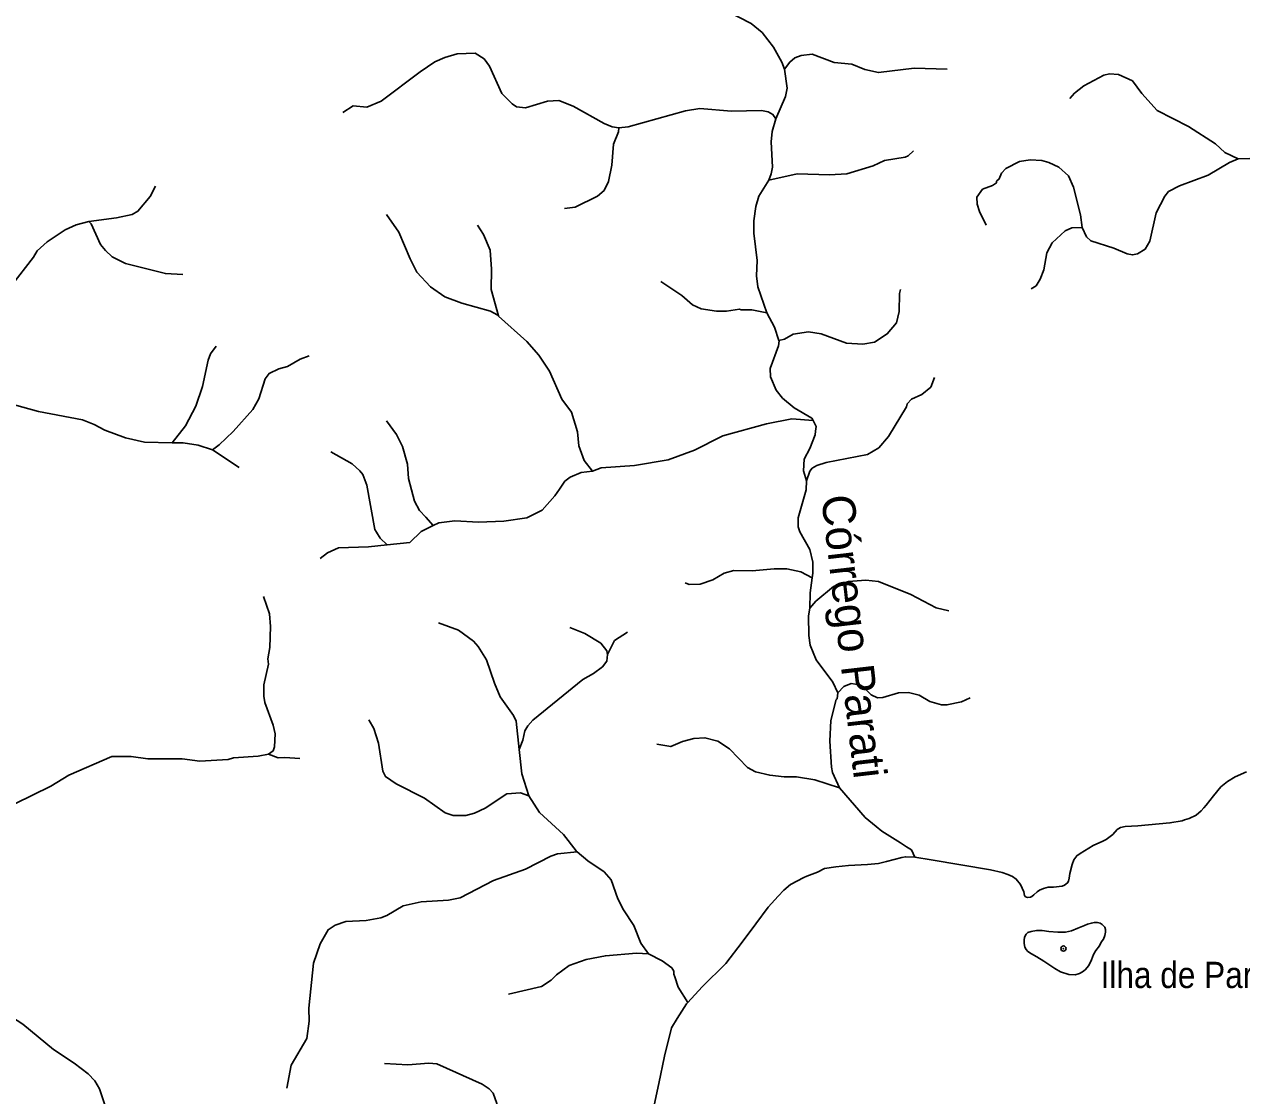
# Model space of a CAD drawing. Extents: x 317.8 to 344.1, y 7676.8 to 7704.8.
# Drawn here: x 330.394 to 334.107, y 7697.935 to 7701.2 of the extents above; entities that cross this region are included whole.
import ezdxf
from ezdxf.enums import TextEntityAlignment as Align

# ---------------------------------------------------------------- set-up
doc = ezdxf.new("R2010")
doc.units = 0
doc.header["$LTSCALE"] = 0.032
doc.header["$PDMODE"] = 32
doc.header["$PDSIZE"] = 0.016
doc.layers.add('2', color=7, linetype='Continuous', lineweight=25)
doc.layers.add('7', color=7, linetype='Continuous', lineweight=25)
doc.layers.add('54', color=7, linetype='Continuous')
doc.layers.add('61', color=7, linetype='Continuous')

msp = doc.modelspace()

# ---------------------------------------------------------------- linework, layer by layer
at = {"layer": '2'}
for points in [[(333.11, 7698.662), (333.1596, 7698.6537), (333.3404, 7698.6227), (333.3766, 7698.6155), (333.3931, 7698.6093), (333.4076, 7698.6031), (333.4189, 7698.5948), (333.4323, 7698.5783), (333.4375, 7698.5669), (333.4427, 7698.5556), (333.4447, 7698.5452), (333.4478, 7698.5411), (333.453, 7698.539), (333.4623, 7698.5401), (333.4664, 7698.5421), (333.4726, 7698.5473), (333.483, 7698.5556), (333.4902, 7698.5607), (333.5026, 7698.5659), (333.516, 7698.57), (333.5326, 7698.57), (333.5594, 7698.5731), (333.5666, 7698.5762), (333.5759, 7698.5835), (333.578, 7698.5886), (333.5801, 7698.5979), (333.5821, 7698.6124), (333.5894, 7698.6392), (333.5945, 7698.6537), (333.6038, 7698.6661), (333.6142, 7698.6733), (333.6534, 7698.6971), (333.6836, 7698.711), (333.6937, 7698.7157), (333.7133, 7698.7312), (333.7268, 7698.7456), (333.7371, 7698.7518), (333.7516, 7698.7549), (333.7898, 7698.757), (333.8879, 7698.7663), (333.9251, 7698.7725), (333.9328, 7698.7751), (333.9468, 7698.7797), (333.9675, 7698.7901), (333.983, 7698.8025), (333.9912, 7698.8118), (333.9985, 7698.82), (334.0212, 7698.8489), (334.0429, 7698.8758), (334.0635, 7698.8923), (334.0873, 7698.9068), (334.1214, 7698.9223)], [(332.4175, 7698.2188), (332.4613, 7698.2663), (332.5336, 7698.3376), (332.5832, 7698.4027), (332.6245, 7698.4585), (332.6627, 7698.5091), (332.6927, 7698.5432), (332.7102, 7698.5607), (332.7309, 7698.5783), (332.7712, 7698.6), (332.7803, 7698.6036), (332.8125, 7698.6165), (332.8342, 7698.6268), (332.8693, 7698.632), (332.9076, 7698.6361), (332.9654, 7698.6392), (332.9985, 7698.6423), (333.0233, 7698.6485), (333.0697, 7698.6609), (333.0813, 7698.663), (333.11, 7698.662)], [(332.2426, 7697.6209), (332.2547, 7697.6465), (332.2733, 7697.6795), (332.2805, 7697.7054), (332.2836, 7697.726), (332.2888, 7697.7694), (332.296, 7697.8242), (332.3001, 7697.8541), (332.3084, 7697.881), (332.3146, 7697.9058), (332.329, 7697.9719), (332.3466, 7698.0556), (332.3673, 7698.1413), (332.3848, 7698.1702), (332.4138, 7698.2147), (332.4175, 7698.2188)]]:
    msp.add_lwpolyline(points, dxfattribs=at)
msp.add_lwpolyline([(333.6732, 7698.3918), (333.662, 7698.3776), (333.6549, 7698.3652), (333.6484, 7698.3487), (333.6401, 7698.3316), (333.6289, 7698.3186), (333.6212, 7698.3126), (333.6123, 7698.3073), (333.5987, 7698.3032), (333.5798, 7698.3044), (333.5544, 7698.3126), (333.5373, 7698.3221), (333.5036, 7698.3446), (333.4823, 7698.3576), (333.4658, 7698.367), (333.4546, 7698.3747), (333.4493, 7698.38), (333.4451, 7698.3877), (333.4428, 7698.3989), (333.4428, 7698.4084), (333.4439, 7698.4184), (333.4493, 7698.4273), (333.4546, 7698.432), (333.4646, 7698.4355), (333.4806, 7698.4379), (333.4977, 7698.4379), (333.519, 7698.4355), (333.5456, 7698.4332), (333.5692, 7698.4332), (333.5875, 7698.4373), (333.607, 7698.445), (333.6271, 7698.4539), (333.6366, 7698.458), (333.6484, 7698.461), (333.6572, 7698.4621), (333.6673, 7698.4621), (333.675, 7698.4604), (333.6815, 7698.4562), (333.6891, 7698.4485), (333.6909, 7698.4409), (333.6909, 7698.4332), (333.6897, 7698.4231), (333.6856, 7698.4119), (333.6785, 7698.4025)], close=True, dxfattribs=at)
at = {"layer": '54'}
msp.add_point((333.563, 7698.3831), dxfattribs=at)
at = {"layer": '7'}
msp.add_line((330.9677, 7699.9037), (331.0485, 7699.8496), dxfattribs=at)
for points in [[(332.7127, 7701.0636), (332.7039, 7701.0855), (332.6788, 7701.1305), (332.6437, 7701.1753), (332.6105, 7701.2027), (332.5375, 7701.2407), (332.4622, 7701.2695), (332.4081, 7701.2981), (332.3644, 7701.3109), (332.3427, 7701.3133), (332.2463, 7701.3044), (332.2335, 7701.3067), (332.1926, 7701.3243), (332.1788, 7701.3361), (332.1388, 7701.3581)], [(332.2074, 7700.8853), (332.1868, 7700.8884), (332.1625, 7700.8976), (332.068, 7700.9506), (332.024, 7700.9685), (331.9895, 7700.9661), (331.9219, 7700.9459), (331.8949, 7700.9493), (331.882, 7700.9583), (331.8504, 7700.99), (331.8122, 7701.0727), (331.7959, 7701.0955), (331.7684, 7701.1121), (331.7143, 7701.1103), (331.6758, 7701.0991), (331.6461, 7701.086), (331.601, 7701.056), (331.482, 7700.9657), (331.4387, 7700.9474), (331.3966, 7700.9522), (331.3648, 7700.932)], [(333.2083, 7701.0632), (333.1073, 7701.0663), (332.9985, 7701.0534), (332.9576, 7701.063), (332.9174, 7701.0786), (332.8633, 7701.0844), (332.7967, 7701.1095), (332.7628, 7701.1056), (332.744, 7701.0979), (332.7283, 7701.0851), (332.7127, 7701.0636)], [(332.6854, 7700.9119), (332.7153, 7700.9805), (332.7199, 7701.0062), (332.7127, 7701.0636)], [(334.0962, 7700.7904), (334.0558, 7700.8097), (334.0268, 7700.8363), (333.9445, 7700.8886), (333.8487, 7700.938), (333.8026, 7700.9895), (333.7734, 7701.0285), (333.7306, 7701.0476), (333.7039, 7701.0492), (333.686, 7701.0457), (333.6256, 7701.0126), (333.5973, 7700.9908), (333.5824, 7700.9744)], [(332.6854, 7700.9119), (332.6771, 7700.9256), (332.6627, 7700.9336), (332.6422, 7700.9376), (332.5509, 7700.936), (332.454, 7700.9433), (332.4099, 7700.937), (332.2358, 7700.8884), (332.2074, 7700.8853)], [(332.6644, 7700.7251), (332.672, 7700.7444), (332.6752, 7700.7648), (332.6719, 7700.8423), (332.6747, 7700.8739), (332.6854, 7700.9119)], [(332.2074, 7700.8853), (332.2061, 7700.8722), (332.1911, 7700.8352), (332.1853, 7700.7714), (332.1757, 7700.7216), (332.1626, 7700.6942), (332.1422, 7700.6763), (332.0742, 7700.6433), (332.0412, 7700.6394)], [(332.6644, 7700.7251), (332.7511, 7700.7446), (332.8493, 7700.7421), (332.9023, 7700.7444), (332.983, 7700.7693), (333.0168, 7700.7851), (333.0805, 7700.7955), (333.0898, 7700.7995), (333.1056, 7700.8146)], [(334.4543, 7700.8018), (334.4243, 7700.8022), (334.3602, 7700.7926), (334.3358, 7700.7841), (334.2942, 7700.7795), (334.1956, 7700.786), (334.1728, 7700.7828), (334.1316, 7700.7909), (334.0962, 7700.7904)], [(333.6198, 7700.5808), (333.6149, 7700.6197), (333.5942, 7700.7044), (333.5786, 7700.7381), (333.5494, 7700.765), (333.519, 7700.7793), (333.4967, 7700.785), (333.4614, 7700.7876), (333.4291, 7700.7827), (333.3872, 7700.7611), (333.3737, 7700.747), (333.367, 7700.7291), (333.3593, 7700.7218), (333.3586, 7700.7172), (333.3465, 7700.709), (333.3163, 7700.698), (333.2988, 7700.6731), (333.2996, 7700.652), (333.3066, 7700.6296), (333.3273, 7700.588)], [(334.0962, 7700.7904), (334.0698, 7700.7794), (334.0044, 7700.7408), (333.917, 7700.7083), (333.8838, 7700.6905), (333.8719, 7700.6763), (333.8462, 7700.626), (333.8268, 7700.5399), (333.8121, 7700.5155), (333.789, 7700.5008), (333.7738, 7700.4976), (333.7571, 7700.5006), (333.7163, 7700.5177), (333.6468, 7700.54), (333.6337, 7700.5525), (333.6198, 7700.5808)], [(332.6587, 7700.3206), (332.6312, 7700.3997), (332.6264, 7700.4336), (332.6287, 7700.4804), (332.6189, 7700.5638), (332.619, 7700.601), (332.6253, 7700.6446), (332.6337, 7700.6768), (332.6644, 7700.7251)], [(330.7942, 7700.707), (330.7776, 7700.676), (330.7401, 7700.6308), (330.7227, 7700.6211), (330.6743, 7700.6102), (330.5901, 7700.599)], [(331.8398, 7700.3113), (331.8363, 7700.3145), (331.8151, 7700.3264), (331.7279, 7700.3507), (331.6766, 7700.3698), (331.6328, 7700.3998), (331.5912, 7700.4448), (331.5705, 7700.4851), (331.5356, 7700.5668), (331.4984, 7700.6206)], [(330.5901, 7700.599), (330.5521, 7700.5887), (330.518, 7700.5741), (330.4634, 7700.537), (330.433, 7700.5098), (330.4213, 7700.4904), (330.3551, 7700.4049), (330.3124, 7700.3604), (330.2822, 7700.334), (330.2402, 7700.3139), (330.1985, 7700.2994), (330.1287, 7700.2979), (330.1009, 7700.293), (330.0589, 7700.2801), (330.0305, 7700.2538), (330.006, 7700.2037), (329.9865, 7700.1871), (329.986, 7700.1867)], [(330.8774, 7700.4373), (330.824, 7700.4405), (330.7023, 7700.4714), (330.662, 7700.4914), (330.6409, 7700.5105), (330.6264, 7700.529), (330.5978, 7700.5926), (330.5901, 7700.599)], [(331.8398, 7700.3113), (331.8398, 7700.3114), (331.8171, 7700.3916), (331.8186, 7700.4542), (331.8145, 7700.5122), (331.7938, 7700.5602), (331.7755, 7700.588)], [(333.6198, 7700.5808), (333.5884, 7700.5797), (333.5682, 7700.5707), (333.5289, 7700.5346), (333.5123, 7700.504), (333.5033, 7700.4522), (333.4924, 7700.4237), (333.4802, 7700.4036), (333.4651, 7700.3941)], [(332.6587, 7700.3206), (332.6128, 7700.3296), (332.5798, 7700.3297), (332.5747, 7700.3321), (332.5352, 7700.3264), (332.5051, 7700.3263), (332.4581, 7700.3332), (332.4318, 7700.3454), (332.3995, 7700.3738), (332.3346, 7700.4169)], [(333.0665, 7700.3924), (333.0631, 7700.3802), (333.0625, 7700.3246), (333.0539, 7700.2902), (333.0259, 7700.2565), (332.9871, 7700.2317), (332.9509, 7700.2252), (332.9014, 7700.2285), (332.8241, 7700.2571), (332.7856, 7700.2628), (332.7387, 7700.2563), (332.7124, 7700.2406), (332.695, 7700.2371)], [(332.695, 7700.2371), (332.6819, 7700.2771), (332.6587, 7700.3206)], [(332.127, 7699.8386), (332.1016, 7699.8713), (332.0845, 7699.9153), (332.081, 7699.958), (332.0624, 7700.0186), (332.0335, 7700.0581), (331.9957, 7700.1435), (331.9633, 7700.1924), (331.9265, 7700.2332), (331.8398, 7700.3113)], [(330.9784, 7700.2197), (330.9619, 7700.1956), (330.9542, 7700.1771), (330.9373, 7700.0969), (330.9172, 7700.0362), (330.8854, 7699.977), (330.8445, 7699.9252)], [(332.7994, 7699.9923), (332.7953, 7699.9998), (332.7422, 7700.0314), (332.7062, 7700.0605), (332.6871, 7700.0851), (332.6696, 7700.1262), (332.6688, 7700.151), (332.6943, 7700.2205), (332.6955, 7700.2357), (332.695, 7700.2371)], [(330.9677, 7699.9037), (330.9879, 7699.9186), (331.0304, 7699.9594), (331.0906, 7700.0264), (331.1088, 7700.0587), (331.1277, 7700.1198), (331.1403, 7700.1362), (331.1699, 7700.1503), (331.196, 7700.1569), (331.2347, 7700.1796), (331.2621, 7700.1895)], [(330.8445, 7699.9252), (330.7604, 7699.927), (330.7019, 7699.94), (330.6389, 7699.9633), (330.6067, 7699.9807), (330.5708, 7699.9944), (330.4365, 7700.0198), (330.2922, 7700.0601), (330.2584, 7700.0737), (330.1936, 7700.0901), (330.1781, 7700.0957)], [(333.17, 7700.1235), (333.1582, 7700.0947), (333.1314, 7700.0722), (333.0999, 7700.0573), (333.086, 7700.0433), (333.0841, 7700.0345), (333.0299, 7699.9436), (332.9998, 7699.9093), (332.9656, 7699.8894), (332.8397, 7699.8652), (332.8104, 7699.8555), (332.7967, 7699.8472), (332.7899, 7699.8385), (332.7789, 7699.8092)], [(331.641, 7699.6728), (331.6183, 7699.6977), (331.5994, 7699.7184), (331.5836, 7699.747), (331.5653, 7699.8157), (331.562, 7699.8596), (331.5472, 7699.9139), (331.5283, 7699.9499), (331.4984, 7699.9915)], [(332.127, 7699.8386), (332.153, 7699.8482), (332.2546, 7699.8553), (332.3575, 7699.873), (332.4373, 7699.9022), (332.5199, 7699.9435), (332.5241, 7699.9456), (332.6573, 7699.9826), (332.7347, 7699.9979), (332.7994, 7699.9923)], [(332.7789, 7699.8092), (332.7705, 7699.8395), (332.7723, 7699.8748), (332.7893, 7699.9076), (332.8058, 7699.9494), (332.8073, 7699.9606), (332.8091, 7699.9747), (332.7994, 7699.9923)], [(330.9677, 7699.9037), (330.9234, 7699.9173), (330.8781, 7699.9245), (330.8445, 7699.9252)], [(331.3289, 7699.8969), (331.3932, 7699.8609), (331.4174, 7699.8393), (331.4256, 7699.8279), (331.438, 7699.7954), (331.4628, 7699.6608), (331.4681, 7699.652), (331.4791, 7699.6336), (331.5005, 7699.6139)], [(332.127, 7699.8386), (332.0922, 7699.8339), (332.0582, 7699.8204), (332.0427, 7699.8078), (332.026, 7699.7837), (332.0115, 7699.7629), (331.9732, 7699.7196), (331.926, 7699.696), (331.8564, 7699.6858), (331.779, 7699.6825), (331.7065, 7699.6874), (331.658, 7699.6809), (331.641, 7699.6728)], [(332.7969, 7699.5127), (332.799, 7699.5273), (332.7982, 7699.5606), (332.7899, 7699.5999), (332.759, 7699.6532), (332.7543, 7699.6687), (332.7544, 7699.6958), (332.7779, 7699.7813), (332.7789, 7699.8092)], [(331.641, 7699.6728), (331.6036, 7699.6549), (331.5695, 7699.6214), (331.5005, 7699.6139)], [(331.5005, 7699.6139), (331.4431, 7699.6076), (331.3518, 7699.6049), (331.3185, 7699.5897), (331.2963, 7699.5725)], [(332.7969, 7699.5127), (332.7618, 7699.5311), (332.7191, 7699.5406), (332.6809, 7699.5406), (332.6137, 7699.5342), (332.5576, 7699.5358), (332.5278, 7699.5276), (332.4932, 7699.5071), (332.4551, 7699.4935), (332.4214, 7699.4927), (332.4096, 7699.4976)], [(332.7893, 7699.4206), (332.7902, 7699.4673), (332.7969, 7699.5127)], [(332.7893, 7699.4206), (332.808, 7699.442), (332.8614, 7699.4868), (332.9079, 7699.5024), (332.96, 7699.5065), (332.9985, 7699.5016), (333.0979, 7699.4626), (333.1753, 7699.4218), (333.2132, 7699.4128)], [(331.1235, 7699.4568), (331.1413, 7699.4037), (331.1447, 7699.365), (331.1421, 7699.3012), (331.1365, 7699.2668), (331.1379, 7699.2496), (331.1243, 7699.187), (331.1243, 7699.1528), (331.1276, 7699.1333), (331.1528, 7699.0644), (331.1583, 7699.0377), (331.157, 7698.9978), (331.153, 7698.986), (331.1384, 7698.976)], [(332.8749, 7699.1624), (332.8596, 7699.1948), (332.809, 7699.2633), (332.7908, 7699.3083), (332.7869, 7699.3378), (332.7853, 7699.3969), (332.7893, 7699.4206)], [(331.6565, 7699.3761), (331.7175, 7699.3538), (331.7632, 7699.3206), (331.7778, 7699.3043), (331.8038, 7699.263), (331.8274, 7699.1925), (331.8449, 7699.1508), (331.8859, 7699.0937), (331.8935, 7699.0764), (331.903, 7698.9897)], [(332.1726, 7699.2791), (332.1707, 7699.2909), (332.1518, 7699.3143), (332.103, 7699.3434), (332.0575, 7699.3615)], [(332.1726, 7699.2791), (332.1934, 7699.3221), (332.2336, 7699.3476)], [(331.903, 7698.9897), (331.9144, 7699.0181), (331.9204, 7699.0465), (331.9295, 7699.0622), (331.9446, 7699.079), (332.0972, 7699.2038), (332.13, 7699.222), (332.1572, 7699.242), (332.1703, 7699.2588), (332.1726, 7699.2791)], [(333.2784, 7699.1471), (333.2521, 7699.1354), (333.2079, 7699.1259), (333.1912, 7699.1259), (333.156, 7699.1362), (333.1234, 7699.1555), (333.09, 7699.1641), (333.0604, 7699.1625), (333.0121, 7699.1487), (332.9959, 7699.1479), (332.9771, 7699.1568), (332.9512, 7699.1822), (332.9418, 7699.1868), (332.9157, 7699.1911), (332.8929, 7699.182), (332.8749, 7699.1624)], [(332.8802, 7698.8731), (332.859, 7698.92), (332.8554, 7698.9363), (332.8504, 7699.015), (332.8538, 7699.0784), (332.8701, 7699.1419), (332.8733, 7699.1444), (332.8749, 7699.1624)], [(331.4446, 7699.0803), (331.4595, 7699.0543), (331.4743, 7699.0092), (331.4871, 7698.9241), (331.4953, 7698.9072), (331.5282, 7698.8856), (331.6143, 7698.8417), (331.6771, 7698.7964), (331.7014, 7698.7885), (331.7401, 7698.7892), (331.7672, 7698.796), (331.7994, 7698.8106), (331.8651, 7698.8544), (331.9067, 7698.8576), (331.9322, 7698.849)], [(332.8802, 7698.8731), (332.8048, 7698.8976), (332.7485, 7698.9065), (332.7116, 7698.9066), (332.6672, 7698.9115), (332.624, 7698.9218), (332.5997, 7698.9346), (332.545, 7698.9918), (332.5088, 7699.0155), (332.4694, 7699.0256), (332.4361, 7699.0231), (332.4016, 7699.0139), (332.3652, 7698.9987), (332.3232, 7699.0061)], [(331.903, 7698.9897), (331.9111, 7698.9161), (331.9322, 7698.849)], [(331.1384, 7698.976), (331.1069, 7698.97), (331.0313, 7698.9644), (331.015, 7698.9596), (330.9289, 7698.9547), (330.8748, 7698.9611), (330.7705, 7698.9611), (330.7191, 7698.9685), (330.6609, 7698.9684), (330.5294, 7698.9114), (330.4749, 7698.8777), (330.365, 7698.8244), (330.3476, 7698.8103), (330.3178, 7698.776), (330.2784, 7698.7163), (330.2734, 7698.6979), (330.2751, 7698.6023), (330.2652, 7698.4894), (330.2555, 7698.431), (330.2363, 7698.373), (330.211, 7698.3257), (330.1755, 7698.274), (330.1407, 7698.2419)], [(331.1384, 7698.976), (331.1677, 7698.9645), (331.1878, 7698.966), (331.2344, 7698.9621)], [(333.11, 7698.662), (333.0994, 7698.6836), (333.0847, 7698.6929), (333.0656, 7698.705), (333.009, 7698.7408), (332.9915, 7698.7552), (332.9579, 7698.783), (332.8802, 7698.8731)], [(331.9322, 7698.849), (331.9648, 7698.7979), (332.0377, 7698.7307), (332.0766, 7698.6812), (332.08, 7698.6782)], [(332.08, 7698.6782), (332.0198, 7698.6719), (331.9996, 7698.6653), (331.9227, 7698.6247), (331.8249, 7698.5911), (331.7232, 7698.538), (331.6869, 7698.5302), (331.6045, 7698.5251), (331.5495, 7698.5129), (331.4994, 7698.4838), (331.481, 7698.4767), (331.4366, 7698.469), (331.3747, 7698.4655), (331.3422, 7698.4548), (331.3199, 7698.4405), (331.296, 7698.3978), (331.2761, 7698.3391), (331.2612, 7698.2018), (331.2628, 7698.1614), (331.2553, 7698.1092), (331.2075, 7698.0281), (331.1944, 7697.9572)], [(332.08, 7698.6782), (332.1126, 7698.6501), (332.1619, 7698.617), (332.1832, 7698.5926), (332.204, 7698.5352), (332.2216, 7698.5014), (332.253, 7698.4534), (332.2736, 7698.3993), (332.2978, 7698.367)], [(332.2978, 7698.367), (332.2613, 7698.3694), (332.1658, 7698.3613), (332.1071, 7698.3499), (332.0553, 7698.3313), (332.0164, 7698.3033), (332.0006, 7698.2867), (331.9712, 7698.2673), (331.8701, 7698.2441)], [(332.2978, 7698.367), (332.3396, 7698.3454), (332.3682, 7698.3242), (332.3744, 7698.3145), (332.3748, 7698.3056), (332.3778, 7698.2968), (332.3883, 7698.2659), (332.4175, 7698.2188)], [(330.7178, 7697.7308), (330.6931, 7697.7578), (330.6708, 7697.794), (330.6556, 7697.8302), (330.6532, 7697.8417), (330.6402, 7697.9038), (330.6225, 7697.9557), (330.6088, 7697.9796), (330.588, 7698.0011), (330.5453, 7698.0338), (330.4827, 7698.0755), (330.3888, 7698.1527), (330.3546, 7698.1749), (330.2399, 7698.2299), (330.1857, 7698.2415), (330.1407, 7698.2419)], [(331.8504, 7697.5113), (331.8025, 7697.6137), (331.7942, 7697.6463), (331.7958, 7697.7392), (331.7892, 7697.7618), (331.7942, 7697.8055), (331.8335, 7697.8787), (331.8349, 7697.911), (331.8241, 7697.9419), (331.8112, 7697.9554), (331.7901, 7697.9694), (331.6523, 7698.0316), (331.6276, 7698.0338), (331.5636, 7698.0289), (331.4919, 7698.033)]]:
    msp.add_lwpolyline(points, dxfattribs=at)

# ---------------------------------------------------------------- texts
at = {"layer": '54', "width": 0.9}
msp.add_text('Ilha de Parati', height=0.08, dxfattribs=at).set_placement((333.6764, 7698.2628))
at = {"layer": '61'}
msp.add_text('Córrego Parati', height=0.1, rotation=276.633, dxfattribs=at).set_placement((332.8743, 7699.3291), align=Align.CENTER)

doc.saveas('drawing.dxf')
